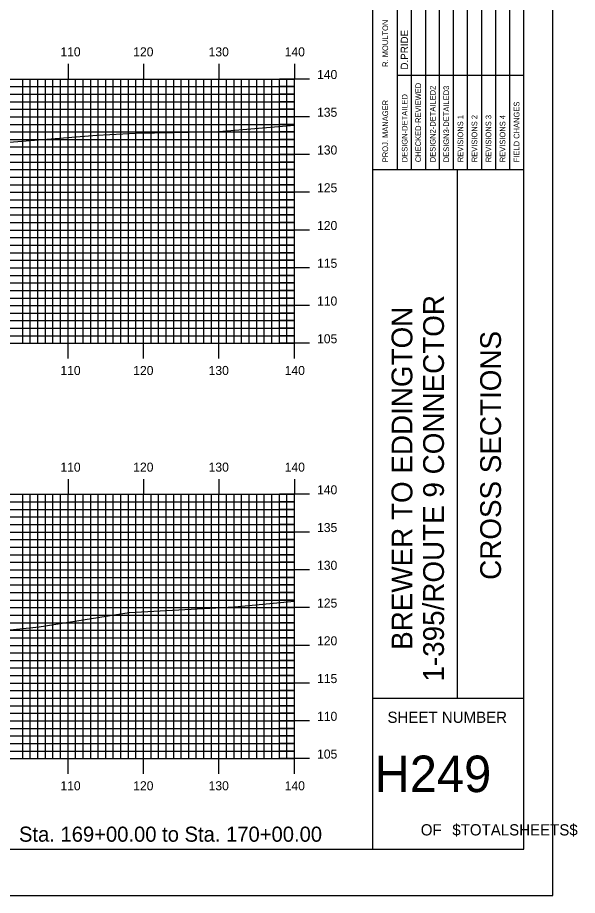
# Model space of a CAD drawing. Extents: x 1782254 to 1782597, y 442591 to 442811.
# Drawn here: x 1782522.7 to 1782596.9, y 442590.5 to 442706.8 of the extents above; entities that cross this region are included whole.
import ezdxf

# ---------------------------------------------------------------- set-up
doc = ezdxf.new("R2010")
doc.units = 0
for name, color, linetype in [('BORDER', 7, 'Continuous'), ('H_V ANNOTATION', 7, 'Continuous'), ('MAJOR', 7, 'Continuous'), ('MINOR', 7, 'Continuous'), ('PLOT BOUNDARY', 7, 'Continuous'), ('S_Roadway_Centerline', 7, 'Continuous')]:
    doc.layers.add(name, color=color, linetype=linetype)

msp = doc.modelspace()

# ---------------------------------------------------------------- linework, layer by layer
at = {"layer": 'BORDER'}
for p, q in [((1782569.83, 442596.67), (1782569.83, 442806.67)), ((1782569.83, 442686.67), (1782589.83, 442686.67)), ((1782569.83, 442686.67), (1782589.83, 442686.67)), ((1782581.02, 442616.67), (1782581.02, 442686.67)), ((1782581.02, 442616.67), (1782581.02, 442686.67)), ((1782569.83, 442616.67), (1782589.83, 442616.67)), ((1782569.83, 442616.67), (1782589.83, 442616.67))]:
    msp.add_line(p, q, dxfattribs=at)
msp.add_lwpolyline([(1782269.83, 442596.67), (1782589.83, 442596.67), (1782589.83, 442806.67), (1782269.83, 442806.67)], close=True, dxfattribs=at)
for points in [[(1782574.93, 442686.68), (1782574.93, 442721.67)], [(1782574.93, 442686.68), (1782574.93, 442721.67)], [(1782576.79, 442721.67), (1782576.79, 442686.68)], [(1782576.79, 442721.67), (1782576.79, 442686.68)], [(1782578.66, 442686.68), (1782578.66, 442721.67)], [(1782578.66, 442686.68), (1782578.66, 442721.67)], [(1782580.52, 442686.68), (1782580.52, 442721.67)], [(1782580.52, 442686.68), (1782580.52, 442721.67)], [(1782582.38, 442686.68), (1782582.38, 442721.67)], [(1782582.38, 442686.68), (1782582.38, 442721.67)], [(1782584.25, 442686.68), (1782584.25, 442721.67)], [(1782584.25, 442686.68), (1782584.25, 442721.67)], [(1782586.11, 442686.68), (1782586.11, 442721.67)], [(1782586.11, 442686.68), (1782586.11, 442721.67)], [(1782587.97, 442686.68), (1782587.97, 442721.67)], [(1782587.97, 442686.68), (1782587.97, 442721.67)], [(1782573.07, 442686.68), (1782573.07, 442720.26)], [(1782573.07, 442686.68), (1782573.07, 442720.26)], [(1782573.06, 442699.17), (1782589.83, 442699.17)], [(1782573.06, 442699.17), (1782589.83, 442699.17)]]:
    msp.add_lwpolyline(points, dxfattribs=at)
at = {"layer": 'MAJOR'}
for p, q in [((1782529.43, 442700.67), (1782529.43, 442698.67)), ((1782539.43, 442700.67), (1782539.43, 442698.67)), ((1782549.43, 442700.67), (1782549.43, 442698.67)), ((1782559.43, 442700.67), (1782559.43, 442698.67)), ((1782279.43, 442698.67), (1782559.43, 442698.67)), ((1782279.43, 442698.67), (1782559.43, 442698.67)), ((1782529.43, 442663.67), (1782529.43, 442698.67)), ((1782539.43, 442663.67), (1782539.43, 442698.67)), ((1782549.43, 442663.67), (1782549.43, 442698.67)), ((1782561.44, 442698.67), (1782557.43, 442698.67)), ((1782559.43, 442663.67), (1782559.43, 442698.67)), ((1782559.43, 442663.67), (1782559.43, 442698.67)), ((1782279.43, 442693.67), (1782559.43, 442693.67)), ((1782561.44, 442693.67), (1782557.43, 442693.67)), ((1782279.43, 442688.67), (1782559.43, 442688.67)), ((1782561.44, 442688.67), (1782557.43, 442688.67)), ((1782279.43, 442683.67), (1782559.43, 442683.67)), ((1782561.44, 442683.67), (1782557.43, 442683.67)), ((1782279.43, 442678.67), (1782559.43, 442678.67)), ((1782561.44, 442678.67), (1782557.43, 442678.67)), ((1782279.43, 442673.67), (1782559.43, 442673.67)), ((1782561.44, 442673.67), (1782557.43, 442673.67)), ((1782279.43, 442668.67), (1782559.43, 442668.67)), ((1782561.44, 442668.67), (1782557.43, 442668.67)), ((1782279.43, 442663.67), (1782559.43, 442663.67)), ((1782279.43, 442663.67), (1782559.43, 442663.67)), ((1782529.43, 442661.66), (1782529.43, 442663.67)), ((1782539.43, 442661.66), (1782539.43, 442663.67)), ((1782549.43, 442661.66), (1782549.43, 442663.67)), ((1782561.44, 442663.67), (1782557.43, 442663.67)), ((1782559.43, 442661.66), (1782559.43, 442663.67)), ((1782529.43, 442645.67), (1782529.43, 442643.67)), ((1782539.43, 442645.67), (1782539.43, 442643.67)), ((1782549.43, 442645.67), (1782549.43, 442643.67)), ((1782559.43, 442645.67), (1782559.43, 442643.67)), ((1782279.43, 442643.67), (1782559.43, 442643.67)), ((1782279.43, 442643.67), (1782559.43, 442643.67)), ((1782529.43, 442608.67), (1782529.43, 442643.67)), ((1782539.43, 442608.67), (1782539.43, 442643.67)), ((1782549.43, 442608.67), (1782549.43, 442643.67)), ((1782561.44, 442643.67), (1782557.43, 442643.67)), ((1782559.43, 442608.67), (1782559.43, 442643.67)), ((1782559.43, 442608.67), (1782559.43, 442643.67)), ((1782279.43, 442638.67), (1782559.43, 442638.67)), ((1782561.44, 442638.67), (1782557.43, 442638.67)), ((1782279.43, 442633.67), (1782559.43, 442633.67)), ((1782561.44, 442633.67), (1782557.43, 442633.67)), ((1782279.43, 442628.67), (1782559.43, 442628.67)), ((1782561.44, 442628.67), (1782557.43, 442628.67)), ((1782279.43, 442623.67), (1782559.43, 442623.67)), ((1782561.44, 442623.67), (1782557.43, 442623.67)), ((1782279.43, 442618.67), (1782559.43, 442618.67)), ((1782561.44, 442618.67), (1782557.43, 442618.67)), ((1782279.43, 442613.67), (1782559.43, 442613.67)), ((1782561.44, 442613.67), (1782557.43, 442613.67)), ((1782279.43, 442608.67), (1782559.43, 442608.67)), ((1782279.43, 442608.67), (1782559.43, 442608.67)), ((1782529.43, 442606.66), (1782529.43, 442608.67)), ((1782539.43, 442606.66), (1782539.43, 442608.67)), ((1782549.43, 442606.66), (1782549.43, 442608.67)), ((1782561.44, 442608.67), (1782557.43, 442608.67)), ((1782559.43, 442606.66), (1782559.43, 442608.67))]:
    msp.add_line(p, q, dxfattribs=at)
at = {"layer": 'MINOR'}
for p, q in [((1782523.43, 442663.67), (1782523.43, 442698.67)), ((1782524.43, 442663.67), (1782524.43, 442698.67)), ((1782525.43, 442663.67), (1782525.43, 442698.67)), ((1782526.43, 442663.67), (1782526.43, 442698.67)), ((1782527.43, 442663.67), (1782527.43, 442698.67)), ((1782528.43, 442663.67), (1782528.43, 442698.67)), ((1782530.43, 442663.67), (1782530.43, 442698.67)), ((1782531.43, 442663.67), (1782531.43, 442698.67)), ((1782532.43, 442663.67), (1782532.43, 442698.67)), ((1782533.43, 442663.67), (1782533.43, 442698.67)), ((1782534.43, 442663.67), (1782534.43, 442698.67)), ((1782535.43, 442663.67), (1782535.43, 442698.67)), ((1782536.43, 442663.67), (1782536.43, 442698.67)), ((1782537.43, 442663.67), (1782537.43, 442698.67)), ((1782538.43, 442663.67), (1782538.43, 442698.67)), ((1782540.43, 442663.67), (1782540.43, 442698.67)), ((1782541.43, 442663.67), (1782541.43, 442698.67)), ((1782542.43, 442663.67), (1782542.43, 442698.67)), ((1782543.43, 442663.67), (1782543.43, 442698.67)), ((1782544.43, 442663.67), (1782544.43, 442698.67)), ((1782545.43, 442663.67), (1782545.43, 442698.67)), ((1782546.43, 442663.67), (1782546.43, 442698.67)), ((1782547.43, 442663.67), (1782547.43, 442698.67)), ((1782548.43, 442663.67), (1782548.43, 442698.67)), ((1782550.43, 442663.67), (1782550.43, 442698.67)), ((1782551.43, 442663.67), (1782551.43, 442698.67)), ((1782552.43, 442663.67), (1782552.43, 442698.67)), ((1782553.43, 442663.67), (1782553.43, 442698.67)), ((1782554.43, 442663.67), (1782554.43, 442698.67)), ((1782555.43, 442663.67), (1782555.43, 442698.67)), ((1782556.43, 442663.67), (1782556.43, 442698.67)), ((1782557.43, 442663.67), (1782557.43, 442698.67)), ((1782558.43, 442663.67), (1782558.43, 442698.67)), ((1782279.43, 442697.67), (1782559.43, 442697.67)), ((1782559.43, 442697.67), (1782557.43, 442697.67)), ((1782279.43, 442696.67), (1782559.43, 442696.67)), ((1782559.43, 442696.67), (1782557.43, 442696.67)), ((1782279.43, 442695.67), (1782559.43, 442695.67)), ((1782559.43, 442695.67), (1782557.43, 442695.67)), ((1782279.43, 442694.67), (1782559.43, 442694.67)), ((1782559.43, 442694.67), (1782557.43, 442694.67)), ((1782279.43, 442692.67), (1782559.43, 442692.67)), ((1782279.43, 442691.67), (1782559.43, 442691.67)), ((1782559.43, 442692.67), (1782557.43, 442692.67)), ((1782559.43, 442691.67), (1782557.43, 442691.67)), ((1782279.43, 442690.67), (1782559.43, 442690.67)), ((1782559.43, 442690.67), (1782557.43, 442690.67)), ((1782279.43, 442689.67), (1782559.43, 442689.67)), ((1782559.43, 442689.67), (1782557.43, 442689.67)), ((1782279.43, 442687.67), (1782559.43, 442687.67)), ((1782559.43, 442687.67), (1782557.43, 442687.67)), ((1782279.43, 442686.67), (1782559.43, 442686.67)), ((1782559.43, 442686.67), (1782557.43, 442686.67)), ((1782279.43, 442685.67), (1782559.43, 442685.67)), ((1782279.43, 442684.67), (1782559.43, 442684.67)), ((1782559.43, 442685.67), (1782557.43, 442685.67)), ((1782559.43, 442684.67), (1782557.43, 442684.67)), ((1782279.43, 442682.67), (1782559.43, 442682.67)), ((1782559.43, 442682.67), (1782557.43, 442682.67)), ((1782279.43, 442681.67), (1782559.43, 442681.67)), ((1782559.43, 442681.67), (1782557.43, 442681.67)), ((1782279.43, 442680.67), (1782559.43, 442680.67)), ((1782559.43, 442680.67), (1782557.43, 442680.67)), ((1782279.43, 442679.67), (1782559.43, 442679.67)), ((1782559.43, 442679.67), (1782557.43, 442679.67)), ((1782279.43, 442677.67), (1782559.43, 442677.67)), ((1782279.43, 442676.67), (1782559.43, 442676.67)), ((1782559.43, 442677.67), (1782557.43, 442677.67)), ((1782559.43, 442676.67), (1782557.43, 442676.67)), ((1782279.43, 442675.67), (1782559.43, 442675.67)), ((1782559.43, 442675.67), (1782557.43, 442675.67)), ((1782279.43, 442674.67), (1782559.43, 442674.67)), ((1782559.43, 442674.67), (1782557.43, 442674.67)), ((1782279.43, 442672.67), (1782559.43, 442672.67)), ((1782559.43, 442672.67), (1782557.43, 442672.67)), ((1782279.43, 442671.67), (1782559.43, 442671.67)), ((1782559.43, 442671.67), (1782557.43, 442671.67)), ((1782279.43, 442670.67), (1782559.43, 442670.67)), ((1782279.43, 442669.67), (1782559.43, 442669.67)), ((1782559.43, 442670.67), (1782557.43, 442670.67)), ((1782559.43, 442669.67), (1782557.43, 442669.67)), ((1782279.43, 442667.67), (1782559.43, 442667.67)), ((1782559.43, 442667.67), (1782557.43, 442667.67)), ((1782279.43, 442666.67), (1782559.43, 442666.67)), ((1782559.43, 442666.67), (1782557.43, 442666.67)), ((1782279.43, 442665.67), (1782559.43, 442665.67)), ((1782559.43, 442665.67), (1782557.43, 442665.67)), ((1782279.43, 442664.67), (1782559.43, 442664.67)), ((1782559.43, 442664.67), (1782557.43, 442664.67)), ((1782523.43, 442608.67), (1782523.43, 442643.67)), ((1782524.43, 442608.67), (1782524.43, 442643.67)), ((1782525.43, 442608.67), (1782525.43, 442643.67)), ((1782526.43, 442608.67), (1782526.43, 442643.67)), ((1782527.43, 442608.67), (1782527.43, 442643.67)), ((1782528.43, 442608.67), (1782528.43, 442643.67)), ((1782530.43, 442608.67), (1782530.43, 442643.67)), ((1782531.43, 442608.67), (1782531.43, 442643.67)), ((1782532.43, 442608.67), (1782532.43, 442643.67)), ((1782533.43, 442608.67), (1782533.43, 442643.67)), ((1782534.43, 442608.67), (1782534.43, 442643.67)), ((1782535.43, 442608.67), (1782535.43, 442643.67)), ((1782536.43, 442608.67), (1782536.43, 442643.67)), ((1782537.43, 442608.67), (1782537.43, 442643.67)), ((1782538.43, 442608.67), (1782538.43, 442643.67)), ((1782540.43, 442608.67), (1782540.43, 442643.67)), ((1782541.43, 442608.67), (1782541.43, 442643.67)), ((1782542.43, 442608.67), (1782542.43, 442643.67)), ((1782543.43, 442608.67), (1782543.43, 442643.67)), ((1782544.43, 442608.67), (1782544.43, 442643.67)), ((1782545.43, 442608.67), (1782545.43, 442643.67)), ((1782546.43, 442608.67), (1782546.43, 442643.67)), ((1782547.43, 442608.67), (1782547.43, 442643.67)), ((1782548.43, 442608.67), (1782548.43, 442643.67)), ((1782550.43, 442608.67), (1782550.43, 442643.67)), ((1782551.43, 442608.67), (1782551.43, 442643.67)), ((1782552.43, 442608.67), (1782552.43, 442643.67)), ((1782553.43, 442608.67), (1782553.43, 442643.67)), ((1782554.43, 442608.67), (1782554.43, 442643.67)), ((1782555.43, 442608.67), (1782555.43, 442643.67)), ((1782556.43, 442608.67), (1782556.43, 442643.67)), ((1782557.43, 442608.67), (1782557.43, 442643.67)), ((1782558.43, 442608.67), (1782558.43, 442643.67)), ((1782279.43, 442642.67), (1782559.43, 442642.67)), ((1782279.43, 442641.67), (1782559.43, 442641.67)), ((1782559.43, 442642.67), (1782557.43, 442642.67)), ((1782559.43, 442641.67), (1782557.43, 442641.67)), ((1782279.43, 442640.67), (1782559.43, 442640.67)), ((1782559.43, 442640.67), (1782557.43, 442640.67)), ((1782279.43, 442639.67), (1782559.43, 442639.67)), ((1782559.43, 442639.67), (1782557.43, 442639.67)), ((1782279.43, 442637.67), (1782559.43, 442637.67)), ((1782559.43, 442637.67), (1782557.43, 442637.67)), ((1782279.43, 442636.67), (1782559.43, 442636.67)), ((1782559.43, 442636.67), (1782557.43, 442636.67)), ((1782279.43, 442635.67), (1782559.43, 442635.67)), ((1782279.43, 442634.67), (1782559.43, 442634.67)), ((1782559.43, 442635.67), (1782557.43, 442635.67)), ((1782559.43, 442634.67), (1782557.43, 442634.67)), ((1782279.43, 442632.67), (1782559.43, 442632.67)), ((1782559.43, 442632.67), (1782557.43, 442632.67)), ((1782279.43, 442631.67), (1782559.43, 442631.67)), ((1782559.43, 442631.67), (1782557.43, 442631.67)), ((1782279.43, 442630.67), (1782559.43, 442630.67)), ((1782559.43, 442630.67), (1782557.43, 442630.67)), ((1782279.43, 442629.67), (1782559.43, 442629.67)), ((1782559.43, 442629.67), (1782557.43, 442629.67)), ((1782279.43, 442627.67), (1782559.43, 442627.67)), ((1782279.43, 442626.67), (1782559.43, 442626.67)), ((1782559.43, 442627.67), (1782557.43, 442627.67)), ((1782559.43, 442626.67), (1782557.43, 442626.67)), ((1782279.43, 442625.67), (1782559.43, 442625.67)), ((1782559.43, 442625.67), (1782557.43, 442625.67)), ((1782279.43, 442624.67), (1782559.43, 442624.67)), ((1782559.43, 442624.67), (1782557.43, 442624.67)), ((1782279.43, 442622.67), (1782559.43, 442622.67)), ((1782559.43, 442622.67), (1782557.43, 442622.67)), ((1782279.43, 442621.67), (1782559.43, 442621.67)), ((1782559.43, 442621.67), (1782557.43, 442621.67)), ((1782279.43, 442620.67), (1782559.43, 442620.67)), ((1782279.43, 442619.67), (1782559.43, 442619.67)), ((1782559.43, 442620.67), (1782557.43, 442620.67)), ((1782559.43, 442619.67), (1782557.43, 442619.67)), ((1782279.43, 442617.67), (1782559.43, 442617.67)), ((1782559.43, 442617.67), (1782557.43, 442617.67)), ((1782279.43, 442616.67), (1782559.43, 442616.67)), ((1782559.43, 442616.67), (1782557.43, 442616.67)), ((1782279.43, 442615.67), (1782559.43, 442615.67)), ((1782559.43, 442615.67), (1782557.43, 442615.67)), ((1782279.43, 442614.67), (1782559.43, 442614.67)), ((1782559.43, 442614.67), (1782557.43, 442614.67)), ((1782279.43, 442612.67), (1782559.43, 442612.67)), ((1782559.43, 442612.67), (1782557.43, 442612.67)), ((1782279.43, 442611.67), (1782559.43, 442611.67)), ((1782559.43, 442611.67), (1782557.43, 442611.67)), ((1782279.43, 442610.67), (1782559.43, 442610.67)), ((1782559.43, 442610.67), (1782557.43, 442610.67)), ((1782279.43, 442609.67), (1782559.43, 442609.67)), ((1782559.43, 442609.67), (1782557.43, 442609.67))]:
    msp.add_line(p, q, dxfattribs=at)
at = {"layer": 'PLOT BOUNDARY'}
msp.add_lwpolyline([(1782253.65, 442590.55), (1782593.65, 442590.55), (1782593.65, 442810.55), (1782253.65, 442810.55)], close=True, dxfattribs=at)
at = {"layer": 'S_Roadway_Centerline'}
for points in [[(1782460.57, 442682.02), (1782474.99, 442684.2), (1782480.09, 442685.13), (1782484.74, 442685.64), (1782491.37, 442686.67), (1782498.17, 442687.04), (1782503.24, 442687.71), (1782508.46, 442688.25), (1782520.59, 442690.21), (1782533.23, 442691.24), (1782538.42, 442691.51), (1782543.38, 442691.61), (1782549.43, 442691.72), (1782559.43, 442692.57)], [(1782465.88, 442620.13), (1782477.35, 442620.52), (1782478.46, 442620.67), (1782479.8, 442620.87), (1782502.69, 442623.5), (1782505.06, 442623.84), (1782514.56, 442625.02), (1782519.15, 442625.46), (1782525.61, 442626.1), (1782527.55, 442626.44), (1782537.55, 442628.03), (1782551.47, 442628.77), (1782559.43, 442629.51)]]:
    msp.add_lwpolyline(points, dxfattribs=at)

# ---------------------------------------------------------------- texts
at = {"layer": 'BORDER'}
for s, height, p in [('R. MOULTON', 0.745, (1782571.84, 442700.28)), ('D.PRIDE', 0.969, (1782574.48, 442699.92)), ('CHECKED-REVIEWED', 0.7455, (1782576.2, 442687.65)), ('CHECKED-REVIEWED', 0.7455, (1782576.2, 442687.65)), ('DESIGN2-DETAILED2', 0.7455, (1782578.13, 442687.65)), ('DESIGN2-DETAILED2', 0.7455, (1782578.13, 442687.65)), ('DESIGN3-DETAILED3', 0.7455, (1782579.92, 442687.65)), ('DESIGN3-DETAILED3', 0.7455, (1782579.92, 442687.65)), ('DESIGN-DETAILED', 0.7455, (1782574.41, 442687.65)), ('DESIGN-DETAILED', 0.7455, (1782574.41, 442687.65)), ('PROJ. MANAGER', 0.7455, (1782571.84, 442687.65)), ('PROJ. MANAGER', 0.7455, (1782571.84, 442687.65)), ('FIELD CHANGES', 0.7455, (1782589.24, 442687.65)), ('FIELD CHANGES', 0.7455, (1782589.24, 442687.65)), ('REVISIONS 1', 0.7455, (1782581.79, 442687.65)), ('REVISIONS 1', 0.7455, (1782581.79, 442687.65)), ('REVISIONS 2', 0.7455, (1782583.65, 442687.65)), ('REVISIONS 2', 0.7455, (1782583.65, 442687.65)), ('REVISIONS 3', 0.7455, (1782585.51, 442687.65)), ('REVISIONS 3', 0.7455, (1782585.51, 442687.65)), ('REVISIONS 4', 0.7455, (1782587.38, 442687.65)), ('REVISIONS 4', 0.7455, (1782587.38, 442687.65)), ('1-395/ROUTE 9 CONNECTOR', 2.7557, (1782579.24, 442618.87)), ('BREWER TO EDDINGTON', 2.7557, (1782575.06, 442623.07)), ('CROSS SECTIONS', 2.7557, (1782586.8, 442632.34)), ('CROSS SECTIONS', 2.7557, (1782586.8, 442632.34))]:
    msp.add_text(s, height=height, rotation=90, dxfattribs=at).set_placement(p)
for s, height, p in [('SHEET NUMBER', 1.4905, (1782571.76, 442613.4)), ('SHEET NUMBER', 1.4905, (1782571.76, 442613.4)), ('H249', 4.839, (1782570.04, 442604.23)), ('OF', 1.491, (1782576.17, 442598.49)), ('OF', 1.491, (1782576.17, 442598.49)), ('$TOTALSHEETS$', 1.4905, (1782580.35, 442598.49)), ('$TOTALSHEETS$', 1.4905, (1782580.35, 442598.49))]:
    msp.add_text(s, height=height, dxfattribs=at).set_placement(p)
at = {"layer": 'H_V ANNOTATION'}
for s, height, p in [('110', 1.2, (1782528.42, 442701.67)), ('120', 1.2, (1782538.07, 442701.67)), ('130', 1.2, (1782548.06, 442701.67)), ('140', 1.2, (1782558.14, 442701.67)), ('140', 1.2, (1782562.43, 442698.67)), ('135', 1.2, (1782562.43, 442693.67)), ('130', 1.2, (1782562.43, 442688.67)), ('125', 1.2, (1782562.43, 442683.67)), ('120', 1.2, (1782562.43, 442678.67)), ('115', 1.2, (1782562.43, 442673.67)), ('110', 1.2, (1782562.43, 442668.67)), ('105', 1.2, (1782562.43, 442663.67)), ('110', 1.2, (1782528.42, 442659.47)), ('120', 1.2, (1782538.07, 442659.47)), ('130', 1.2, (1782548.06, 442659.47)), ('140', 1.2, (1782558.14, 442659.47)), ('110', 1.2, (1782528.42, 442646.67)), ('120', 1.2, (1782538.07, 442646.67)), ('130', 1.2, (1782548.06, 442646.67)), ('140', 1.2, (1782558.14, 442646.67)), ('140', 1.2, (1782562.43, 442643.67)), ('135', 1.2, (1782562.43, 442638.67)), ('130', 1.2, (1782562.43, 442633.67)), ('125', 1.2, (1782562.43, 442628.67)), ('120', 1.2, (1782562.43, 442623.67)), ('115', 1.2, (1782562.43, 442618.67)), ('110', 1.2, (1782562.43, 442613.67)), ('105', 1.2, (1782562.43, 442608.67)), ('110', 1.2, (1782528.42, 442604.47)), ('120', 1.2, (1782538.07, 442604.47)), ('130', 1.2, (1782548.06, 442604.47)), ('140', 1.2, (1782558.14, 442604.47)), ('Sta. 169+00.00 to Sta. 170+00.00', 2.0004, (1782522.93, 442597.66))]:
    msp.add_text(s, height=height, dxfattribs=at).set_placement(p)

doc.saveas('drawing.dxf')
